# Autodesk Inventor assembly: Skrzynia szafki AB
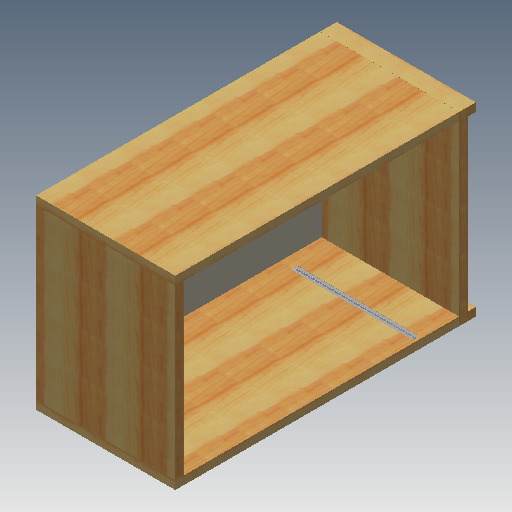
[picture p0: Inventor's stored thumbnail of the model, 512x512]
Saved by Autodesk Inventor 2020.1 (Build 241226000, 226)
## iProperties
Created: 2005-10
Part Number: Skrzynia szafki AB
Document SubType Name: Assembly
Designer: F.Stasiak
Manager: www.cadconsulting.pl
Company: Fabian Stasiak CAD Consulting
Author: F.Stasiak
Subject: Zbiór ćwiczeń. Autodesk Inventor 2020. Kurs podstawowy
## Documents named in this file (8)
- C:\2020_Kurs_podstawowy\R6 Zespoły\Szyki\Skrzynia szafki AB.iam
- C:\2020_Kurs_podstawowy\R6 Zespoły\Szyki\Wieniec dolny AB.ipt
- C:\2020_Kurs_podstawowy\R6 Zespoły\Szyki\Bok LEWY AB.ipt
- C:\2020_Kurs_podstawowy\R6 Zespoły\Szyki\Tył.ipt
- C:\2020_Kurs_podstawowy\R6 Zespoły\Szyki\Wieniec górny AB.ipt
- C:\2020_Kurs_podstawowy\R6 Zespoły\Szyki\Szyna1.ipt
- C:\2020_Kurs_podstawowy\R6 Zespoły\Szyki\Wkręt M3x8.ipt
- C:\2020_Kurs_podstawowy\R6 Zespoły\Szyki\Bok PRAWY AB.ipt
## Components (11 placed, 7 different names)
1. Wieniec dolny AB:1 — Wstaw:1, Wstaw:2, Wstaw:8, Wstaw:9, Zestawiający:8
2. Bok LEWY AB:1 — Wstaw:1, Wstaw:2, Wstaw:3, Zestawiający:4, Wstaw:4, Wstaw:5, Zestawiający:5, Zestawiający:6
3. Bok PRAWY AB:1 — Wstaw:8, Wstaw:9, Wstaw:10, Wstaw:11, Zestawiający:9
4. Tył:1 — Zestawiający:5, Zestawiający:6, Zestawiający:7, Zestawiający:8, Zestawiający:9
5. Wieniec górny AB:1 — Wstaw:3, Zestawiający:4, Zestawiający:7
6. Szyna1:1 — Wstaw:4, Wstaw:5, Wstaw:6, Wstaw:7
7. Wkręt M3x8:1 — Wstaw:6
8. Wkręt M3x8:2 — Wstaw:7
9. Szyna1:2 — Wstaw:10, Wstaw:11, Wstaw:12, Wstaw:13
10. Wkręt M3x8:4 — Wstaw:13
11. Wkręt M3x8:5 — Wstaw:12
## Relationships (19: Insert 13, Mate 6)
- Wstaw:1 [Insert]: Wieniec dolny AB:1 ↔ Bok LEWY AB:1
- Wstaw:2 [Insert]: Wieniec dolny AB:1 ↔ Bok LEWY AB:1
- Wstaw:3 [Insert]: Bok LEWY AB:1 ↔ Wieniec górny AB:1
- Zestawiający:4 [Mate]: Bok LEWY AB:1 ↔ Wieniec górny AB:1
- Wstaw:4 [Insert]: Bok LEWY AB:1 ↔ Szyna1:1
- Wstaw:5 [Insert]: Bok LEWY AB:1 ↔ Szyna1:1
- Wstaw:6 [Insert]: Szyna1:1 ↔ Wkręt M3x8:1
- Wstaw:7 [Insert]: Szyna1:1 ↔ Wkręt M3x8:2
- Wstaw:8 [Insert]: Wieniec dolny AB:1 ↔ Bok PRAWY AB:1
- Wstaw:9 [Insert]: Wieniec dolny AB:1 ↔ Bok PRAWY AB:1
- Wstaw:10 [Insert]: Bok PRAWY AB:1 ↔ Szyna1:2
- Wstaw:11 [Insert]: Bok PRAWY AB:1 ↔ Szyna1:2
- Wstaw:12 [Insert]: Szyna1:2 ↔ Wkręt M3x8:5
- Wstaw:13 [Insert]: Szyna1:2 ↔ Wkręt M3x8:4
- Zestawiający:5 [Mate]: Bok LEWY AB:1 ↔ Tył:1
- Zestawiający:6 [Mate]: Bok LEWY AB:1 ↔ Tył:1
- Zestawiający:7 [Mate]: Tył:1 ↔ Wieniec górny AB:1
- Zestawiający:8 [Mate]: Wieniec dolny AB:1 ↔ Tył:1
- Zestawiający:9 [Mate]: Bok PRAWY AB:1 ↔ Tył:1
